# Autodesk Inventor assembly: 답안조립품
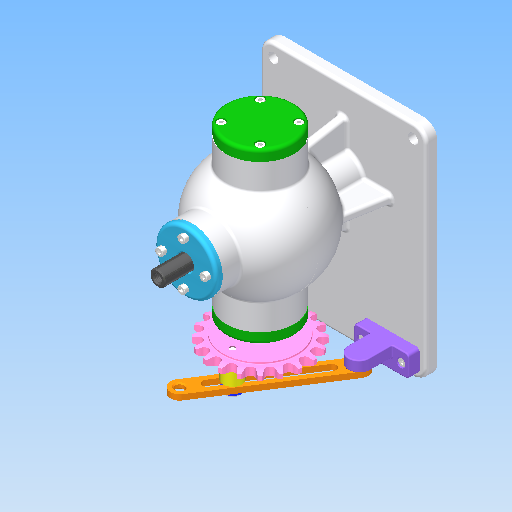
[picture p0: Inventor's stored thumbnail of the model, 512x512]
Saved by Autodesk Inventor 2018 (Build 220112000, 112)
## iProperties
Created: 2022-09
Part Number: 답안조립품
Material: 일반
Document SubType Name: Assembly
Designer: home
Author: home
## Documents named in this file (20)
- C:\Users\kimgi\Desktop\620906V1007\답안조립품.iam
- C:\Users\kimgi\Desktop\620906V1007\본체.ipt
- C:\Users\kimgi\Desktop\620906V1007\본체커버.ipt
- C:\Users\kimgi\Desktop\620906V1007\앞커버.ipt
- C:\Users\kimgi\Desktop\620906V1007\뒤커버.ipt
- C:\Users\kimgi\Desktop\620906V1007\볼트 M4x12.ipt
- C:\Users\kimgi\Desktop\620906V1007\슬라이드 커버.ipt
- C:\Users\kimgi\Desktop\620906V1007\베어링 6202.ipt
- C:\Users\kimgi\Desktop\620906V1007\오일실.ipt
- C:\Users\kimgi\Desktop\620906V1007\축.ipt
- C:\Users\kimgi\Desktop\620906V1007\키 3x3.ipt
- C:\Users\kimgi\Desktop\620906V1007\스프로킷.ipt
- C:\Users\kimgi\Desktop\620906V1007\와셔 8x17.ipt
- C:\Users\kimgi\Desktop\620906V1007\너트 M8x1.ipt
- C:\Users\kimgi\Desktop\620906V1007\힌지.ipt
- C:\Users\kimgi\Desktop\620906V1007\커넥트 암.ipt
- C:\Users\kimgi\Desktop\620906V1007\칼라.ipt
- C:\Users\kimgi\Desktop\620906V1007\연결 핀.ipt
- C:\Users\kimgi\Desktop\620906V1007\가변스프링.ipt
- C:\Users\kimgi\Desktop\620906V1007\슬라이드.ipt
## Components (1 placed, 1 different names)
1. 가변스프링:1
